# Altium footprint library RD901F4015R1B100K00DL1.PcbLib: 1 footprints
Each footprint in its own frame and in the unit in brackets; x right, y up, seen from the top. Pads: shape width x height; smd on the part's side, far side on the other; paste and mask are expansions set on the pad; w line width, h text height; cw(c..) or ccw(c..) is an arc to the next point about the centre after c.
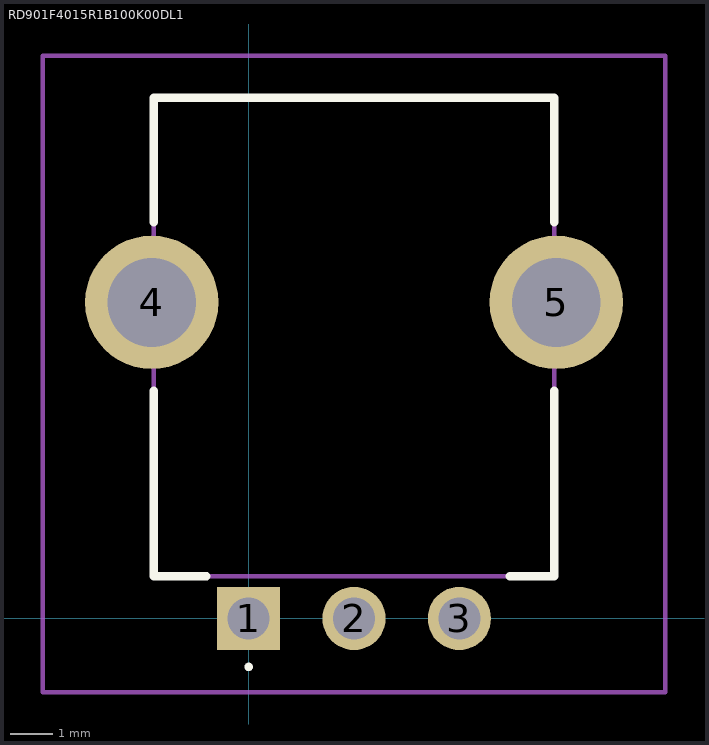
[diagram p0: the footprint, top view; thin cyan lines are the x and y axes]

## RD901F4015R1B100K00DL1 [mm]
pads (5):
  rect 1.5x1.5 hole 1: 1(0,0)
  round 1.5 hole 1: 2(2.5,0) 3(5,0)
  round 3.165 hole 2.11: 4(-2.3,7.5) 5(7.3,7.5)
Top Overlay:
  lines w0.1: 0,-1.2 0,-1.2 ; 0,-1.2 ccw(c0,-1.15) 0,-1.1 ; 0,-1.2 cw(c0,-1.15) 0,-1.1 ; 0,-1.1 0,-1.1
  lines w0.2: -2.25,5.4 -2.25,1 -1,1 ; -2.25,9.4 -2.25,12.35 7.25,12.35 7.25,9.4 ; 6.2,1 7.25,1 7.25,5.4
Mechanical 15:
  lines w0.1: -2.25,1 7.25,1 7.25,12.35 -2.25,12.35 -2.25,1
Mechanical 20:
  lines w0.1: -4.883,-1.75 9.883,-1.75 9.883,13.35 -4.883,13.35 -4.883,-1.75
